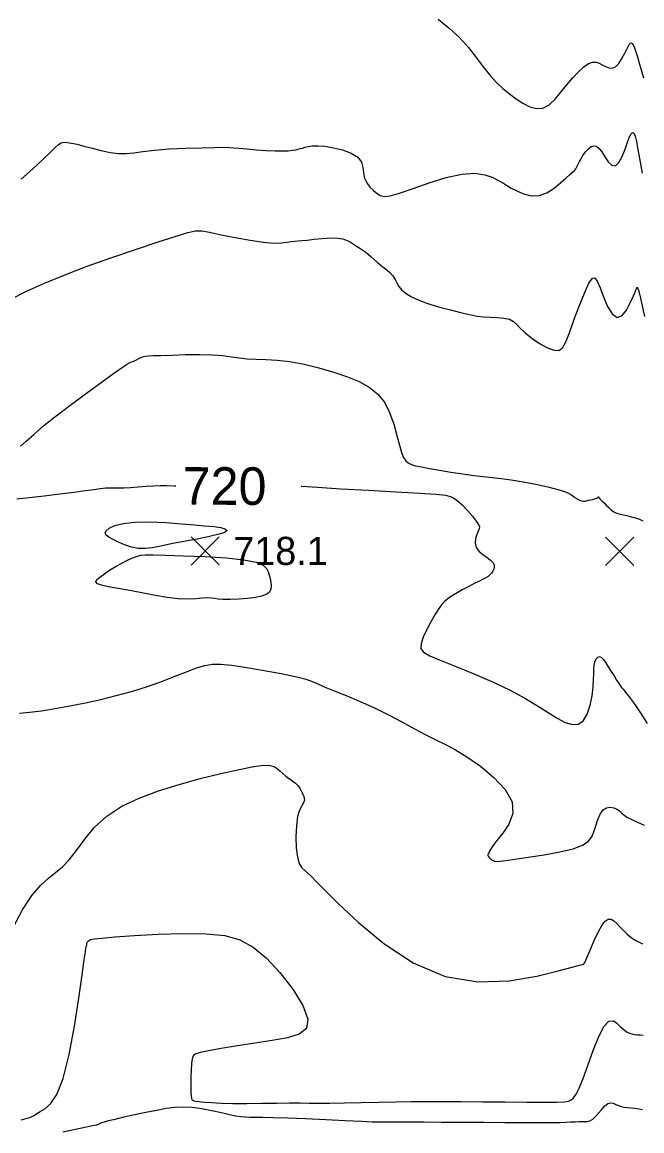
# Model space of a CAD drawing. Extents: x 2566142 to 2571431, y 418755 to 421584.
# Drawn here: x 2570491 to 2570821, y 419211 to 419801 of the extents above; entities that cross this region are included whole.
import ezdxf

# ---------------------------------------------------------------- set-up
doc = ezdxf.new("R2010")
doc.units = 0
for name, color, linetype in [('Contour_ADS_Label_Major', 7, 'Continuous'), ('Contour_ADS_Major', 7, 'Continuous'), ('Contour_ADS_Minor', 7, 'Continuous'), ('Contour_ADS_Spot_Elevation', 7, 'Continuous')]:
    doc.layers.add(name, color=color, linetype=linetype)

# ---------------------------------------------------------------- blocks, each defined once
blk = doc.blocks.new('S750')
at = {"layer": 'Contour_ADS_Spot_Elevation'}
for p, q in [((-0.5, 0.498), (0.5, -0.498)), ((-0.498, -0.5), (0.498, 0.5))]:
    blk.add_line(p, q, dxfattribs=at)

msp = doc.modelspace()

# ---------------------------------------------------------------- linework, layer by layer
at = {"layer": 'Contour_ADS_Major'}
for points in [[(2570488.33, 419547.23), (2570494.91, 419547.98), (2570502.85, 419548.9), (2570511.1, 419549.89), (2570518.65, 419550.84), (2570524.68, 419551.67), (2570529.29, 419552.33), (2570532.8, 419552.81), (2570535.53, 419553.08), (2570537.82, 419553.16), (2570539.98, 419553.11), (2570542.33, 419553.06), (2570545.19, 419553.11), (2570548.77, 419553.32), (2570552.83, 419553.65), (2570557.04, 419553.99), (2570561.03, 419554.26), (2570564.61, 419554.36), (2570568.09, 419554.33), (2570571.93, 419554.2), (2570572.86, 419554.16)], [(2570639.53, 419553.98), (2570639.84, 419553.95), (2570648.19, 419553.41), (2570660.55, 419552.68), (2570675.25, 419551.85), (2570689.99, 419551.04), (2570702.51, 419550.33), (2570711.11, 419549.79), (2570716.46, 419549.17), (2570719.78, 419548.18), (2570722.33, 419546.53), (2570725.08, 419544.03), (2570727.94, 419541.04), (2570730.57, 419538.03), (2570732.62, 419535.47), (2570733.83, 419533.7), (2570734.29, 419532.46), (2570734.17, 419531.39), (2570733.64, 419530.09), (2570732.91, 419528.28), (2570732.27, 419526.09), (2570732.06, 419523.74), (2570732.59, 419521.46), (2570734.06, 419519.41), (2570736.15, 419517.62), (2570738.38, 419516.03), (2570740.3, 419514.61), (2570741.54, 419513.33), (2570742.15, 419512.15), (2570742.25, 419511.03), (2570741.99, 419509.94), (2570741.5, 419508.86), (2570740.8, 419507.82), (2570739.94, 419506.85), (2570738.94, 419505.98), (2570737.78, 419505.22), (2570736.34, 419504.46), (2570734.44, 419503.55), (2570731.92, 419502.33), (2570728.7, 419500.71), (2570725.11, 419498.79), (2570721.54, 419496.74), (2570718.42, 419494.72), (2570716.02, 419492.81), (2570714.15, 419490.82), (2570712.47, 419488.48), (2570710.67, 419485.53), (2570708.54, 419481.83), (2570706.34, 419477.74), (2570704.47, 419473.73), (2570703.31, 419470.29), (2570703.25, 419467.73), (2570704.67, 419465.73), (2570707.96, 419463.79), (2570713.5, 419461.42), (2570721.43, 419458.25), (2570730.92, 419454.4), (2570740.93, 419450.13), (2570750.38, 419445.69), (2570758.44, 419441.32), (2570765.16, 419437.22), (2570770.82, 419433.56), (2570775.7, 419430.53), (2570780.01, 419428.34), (2570783.79, 419427.22), (2570787.02, 419427.45), (2570789.66, 419429.28), (2570791.72, 419432.8), (2570793.23, 419437.47), (2570794.25, 419442.55), (2570794.85, 419447.32), (2570795.09, 419451.2), (2570795.13, 419454.27), (2570795.14, 419456.72), (2570795.31, 419458.78), (2570795.75, 419460.61), (2570796.44, 419462.09), (2570797.31, 419463.06), (2570798.28, 419463.37), (2570799.29, 419462.9), (2570800.37, 419461.74), (2570801.56, 419460.02), (2570802.89, 419457.9), (2570804.38, 419455.51), (2570805.91, 419453.1), (2570807.31, 419450.88), (2570808.44, 419449.11), (2570809.22, 419447.92), (2570809.88, 419446.99), (2570810.7, 419445.94), (2570812.01, 419444.35), (2570814.02, 419441.87), (2570816.68, 419438.34), (2570819.89, 419433.66), (2570823.51, 419427.73)]]:
    msp.add_lwpolyline(points, dxfattribs=at)
at = {"layer": 'Contour_ADS_Minor'}
for points in [[(2570712.43, 419802.4), (2570718.23, 419797.74), (2570723.68, 419792.69), (2570728.44, 419787.42), (2570732.59, 419782.14), (2570736.32, 419777.12), (2570739.85, 419772.6), (2570743.33, 419768.77), (2570746.81, 419765.51), (2570750.32, 419762.69)], [(2570750.32, 419762.69), (2570753.87, 419760.12), (2570757.47, 419757.74), (2570761.08, 419755.84), (2570764.64, 419754.84), (2570768.08, 419755.11), (2570771.38, 419756.92), (2570774.56, 419759.91), (2570777.69, 419763.61), (2570780.8, 419767.52), (2570783.93, 419771.21), (2570786.98, 419774.44), (2570789.84, 419777.03), (2570792.38, 419778.78), (2570794.53, 419779.58), (2570796.37, 419779.6), (2570798.05, 419779.05), (2570799.68, 419778.18), (2570801.38, 419777.23), (2570803.14, 419776.51), (2570804.93, 419776.35), (2570806.73, 419777.07), (2570808.49, 419778.88), (2570810.16, 419781.44), (2570811.67, 419784.28), (2570812.94, 419786.92), (2570813.95, 419788.92), (2570814.82, 419789.88), (2570815.72, 419789.42), (2570816.84, 419787.17), (2570818.28, 419782.95), (2570819.91, 419777.35), (2570821.55, 419771.17)], [(2570686.92, 419708.47), (2570691.89, 419709.84), (2570699.05, 419712.33), (2570707.65, 419715.35), (2570716.64, 419718.17), (2570724.97, 419720.05), (2570731.8, 419720.45), (2570737.13, 419719.7), (2570741.15, 419718.32), (2570744.04, 419716.86), (2570746.06, 419715.72), (2570747.63, 419714.79), (2570749.21, 419713.84), (2570751.3, 419712.63), (2570754.23, 419711.05), (2570757.86, 419709.5), (2570761.92, 419708.5), (2570766.13, 419708.57), (2570770.24, 419710.05), (2570774.07, 419712.51), (2570777.46, 419715.34), (2570780.25, 419717.93), (2570782.34, 419719.81), (2570783.83, 419721.09), (2570784.86, 419722.03), (2570785.58, 419722.86), (2570786.15, 419723.82), (2570786.69, 419724.96), (2570787.32, 419726.33), (2570788.19, 419727.97), (2570789.37, 419729.86), (2570790.78, 419731.79), (2570792.3, 419733.49), (2570793.81, 419734.68), (2570795.22, 419735.15), (2570796.57, 419734.84), (2570797.94, 419733.73), (2570799.43, 419731.82), (2570801.1, 419729.23), (2570802.89, 419726.61), (2570804.76, 419724.75), (2570806.65, 419724.44), (2570808.48, 419726.19), (2570810.21, 419729.44), (2570811.78, 419733.33), (2570813.13, 419737.02), (2570814.21, 419739.8), (2570815.09, 419741.52), (2570815.82, 419742.17), (2570816.47, 419741.72), (2570817.12, 419740.13), (2570817.82, 419737.32), (2570818.65, 419733.15), (2570819.66, 419727.5), (2570820.88, 419720.44)], [(2570490.64, 419717.28), (2570496.87, 419722.8), (2570502.02, 419727.68), (2570505.96, 419731.57), (2570508.67, 419734.25), (2570510.49, 419735.86), (2570511.88, 419736.67), (2570513.28, 419736.93), (2570515.07, 419736.87), (2570517.4, 419736.51), (2570520.34, 419735.87), (2570523.97, 419734.95), (2570528.31, 419733.78), (2570533.06, 419732.57), (2570537.87, 419731.54), (2570542.39, 419730.95), (2570546.44, 419730.95), (2570550.51, 419731.4), (2570555.29, 419732.1), (2570561.47, 419732.82), (2570569.4, 419733.4), (2570578.21, 419733.81), (2570586.7, 419734.08), (2570593.69, 419734.23), (2570598.35, 419734.28), (2570601.35, 419734.24), (2570603.76, 419734.08), (2570606.62, 419733.81), (2570610.71, 419733.43), (2570615.66, 419733.02), (2570620.86, 419732.65), (2570625.65, 419732.41), (2570629.54, 419732.36), (2570632.56, 419732.46), (2570634.86, 419732.68), (2570636.61, 419732.95), (2570637.97, 419733.25), (2570639.13, 419733.56), (2570640.27, 419733.9), (2570641.58, 419734.29), (2570643.24, 419734.69), (2570645.43, 419735.01), (2570648.3, 419735.1), (2570652.03, 419734.83), (2570656.63, 419734.09), (2570661.56, 419732.86), (2570666.11, 419731.16), (2570669.6, 419728.99), (2570671.54, 419726.4), (2570672.36, 419723.55), (2570672.69, 419720.63), (2570673.2, 419717.83), (2570674.36, 419715.31), (2570676.05, 419713.11), (2570677.98, 419711.26), (2570679.87, 419709.76), (2570681.61, 419708.66), (2570683.72, 419708.16), (2570686.92, 419708.47)], [(2570484.67, 419653.26), (2570493.41, 419657.68), (2570502.93, 419662), (2570513.46, 419666.33), (2570525.25, 419670.8), (2570538.26, 419675.43), (2570551.44, 419679.93), (2570563.47, 419683.93), (2570573.03, 419687.04), (2570579.27, 419689), (2570583.28, 419689.87), (2570586.6, 419689.84), (2570590.78, 419689.08), (2570596.95, 419687.79), (2570604.48, 419686.27), (2570612.32, 419684.82), (2570619.42, 419683.77), (2570624.95, 419683.34), (2570629.03, 419683.4), (2570632.01, 419683.73), (2570634.24, 419684.11), (2570636.07, 419684.37), (2570637.85, 419684.54), (2570639.96, 419684.71), (2570642.76, 419684.97), (2570646.48, 419685.37)], [(2570646.48, 419685.37), (2570650.74, 419685.78), (2570655.03, 419686.05), (2570658.83, 419686), (2570661.77, 419685.54), (2570663.99, 419684.75), (2570665.77, 419683.75), (2570667.37, 419682.67), (2570669.03, 419681.63), (2570670.73, 419680.6), (2570672.4, 419679.56), (2570673.96, 419678.45), (2570675.38, 419677.25), (2570676.78, 419675.94), (2570678.28, 419674.53), (2570680.05, 419673), (2570682.15, 419671.36), (2570684.4, 419669.62), (2570686.53, 419667.8), (2570688.29, 419665.93), (2570689.52, 419664.03), (2570690.47, 419662.11), (2570691.52, 419660.21), (2570693.03, 419658.33), (2570695.28, 419656.51), (2570698.24, 419654.75), (2570701.78, 419653.1), (2570705.78, 419651.57), (2570710.11, 419650.18), (2570714.56, 419648.93), (2570718.92, 419647.8), (2570722.97, 419646.79), (2570726.58, 419645.88), (2570729.9, 419645.11), (2570733.14, 419644.51), (2570736.52, 419644.11), (2570740.18, 419643.91), (2570743.89, 419643.75), (2570747.35, 419643.45), (2570750.24, 419642.82), (2570752.38, 419641.69), (2570754.16, 419640.07), (2570756.08, 419638), (2570758.64, 419635.51), (2570762.18, 419632.69), (2570766.31, 419629.93), (2570770.45, 419627.64), (2570774.02, 419626.28), (2570776.63, 419626.22), (2570778.55, 419627.66), (2570780.25, 419630.76), (2570782.17, 419635.66), (2570784.63, 419642.3), (2570787.42, 419649.7), (2570790.19, 419656.65), (2570792.6, 419661.95), (2570794.4, 419664.67), (2570795.78, 419664.91), (2570797.04, 419663.06), (2570798.48, 419659.47), (2570800.32, 419654.66), (2570802.52, 419649.66), (2570804.96, 419645.61), (2570807.52, 419643.68), (2570810.08, 419644.62), (2570812.49, 419647.66), (2570814.59, 419651.61), (2570816.24, 419655.28), (2570817.31, 419657.76), (2570817.93, 419659.11), (2570818.22, 419659.68), (2570818.35, 419659.78), (2570818.44, 419659.7), (2570818.51, 419659.53), (2570818.58, 419659.31), (2570818.66, 419659.08), (2570818.74, 419658.86), (2570818.84, 419658.64), (2570818.94, 419658.38), (2570819.04, 419658.05), (2570819.18, 419657.44), (2570819.57, 419655.65), (2570820.45, 419651.63), (2570822.06, 419644.32)], [(2570547.91, 419619.4), (2570548.97, 419619.91), (2570549.9, 419620.3), (2570550.88, 419620.72), (2570552, 419621.26), (2570553.22, 419621.87), (2570554.46, 419622.45), (2570555.62, 419622.91), (2570556.74, 419623.19), (2570558.27, 419623.34), (2570560.78, 419623.44), (2570564.85, 419623.57), (2570570.79, 419623.78), (2570577.95, 419623.98), (2570585.42, 419624.07), (2570592.28, 419623.94), (2570597.87, 419623.5), (2570602.47, 419622.89), (2570606.6, 419622.26), (2570610.78, 419621.79), (2570615.45, 419621.56), (2570620.75, 419621.4), (2570626.76, 419621.05), (2570633.55, 419620.27), (2570641.09, 419618.88), (2570649, 419616.96), (2570656.82, 419614.69), (2570664.08, 419612.23), (2570670.39, 419609.66), (2570675.74, 419606.76), (2570680.17, 419603.22), (2570683.76, 419598.73), (2570686.58, 419593.17), (2570688.75, 419587.04), (2570690.43, 419581.04), (2570691.77, 419575.85), (2570692.9, 419571.99), (2570693.97, 419569.33), (2570695.11, 419567.57), (2570696.45, 419566.4), (2570698.13, 419565.56), (2570700.4, 419564.88), (2570703.51, 419564.23), (2570707.69, 419563.48), (2570713.06, 419562.54), (2570719.18, 419561.51), (2570725.47, 419560.52), (2570731.36, 419559.7), (2570736.45, 419559.12), (2570741.1, 419558.67), (2570745.85, 419558.17), (2570751.23, 419557.44), (2570757.58, 419556.35), (2570764.34, 419555.02), (2570770.73, 419553.62), (2570775.98, 419552.32), (2570779.52, 419551.25), (2570781.67, 419550.36), (2570782.98, 419549.58), (2570783.97, 419548.83), (2570785.08, 419548.04), (2570786.31, 419547.28), (2570787.54, 419546.64), (2570788.68, 419546.19), (2570789.64, 419546.02), (2570790.49, 419546.06), (2570791.33, 419546.23), (2570792.26, 419546.48), (2570793.34, 419546.72), (2570794.48, 419546.96), (2570795.55, 419547.2), (2570796.41, 419547.45), (2570796.98, 419547.72), (2570797.3, 419547.96), (2570797.46, 419548.16), (2570797.53, 419548.29), (2570797.59, 419548.31), (2570797.68, 419548.22), (2570797.83, 419548.03), (2570798.08, 419547.74), (2570798.45, 419547.34), (2570798.98, 419546.79), (2570799.7, 419546.07), (2570800.65, 419545.12), (2570801.82, 419543.93), (2570803.14, 419542.65), (2570804.48, 419541.43), (2570805.74, 419540.43), (2570806.85, 419539.78), (2570807.94, 419539.39), (2570809.17, 419539.1), (2570810.73, 419538.8), (2570812.72, 419538.36), (2570814.98, 419537.79), (2570817.29, 419537.13), (2570819.43, 419536.4), (2570821.21, 419535.63)], [(2570490.16, 419575.22), (2570493.24, 419577.9), (2570497.26, 419581.55), (2570502.71, 419586.24), (2570509.84, 419591.92), (2570517.92, 419598.07), (2570525.98, 419604.05), (2570533.06, 419609.21), (2570538.41, 419613.07), (2570542.2, 419615.76), (2570544.8, 419617.53), (2570546.59, 419618.66), (2570547.91, 419619.4)], [(2570489.66, 419433.3), (2570494.99, 419433.73), (2570501.41, 419434.53), (2570508.7, 419435.68), (2570516.57, 419437.11), (2570524.75, 419438.76), (2570532.98, 419440.58), (2570541.16, 419442.58), (2570549.25, 419444.79), (2570557.18, 419447.27), (2570564.85, 419449.99), (2570572.03, 419452.74), (2570578.47, 419455.28), (2570583.88, 419457.33), (2570588.2, 419458.69), (2570592.16, 419459.35), (2570596.68, 419459.35), (2570602.67, 419458.73), (2570610.7, 419457.56), (2570619.84, 419456.03)], [(2570619.84, 419456.03), (2570628.81, 419454.38), (2570636.31, 419452.82), (2570641.47, 419451.5), (2570645, 419450.29), (2570648.06, 419448.97), (2570651.76, 419447.33), (2570656.99, 419445.2), (2570663.51, 419442.58), (2570670.83, 419439.53), (2570678.45, 419436.1), (2570685.94, 419432.37), (2570693.08, 419428.56), (2570699.74, 419424.92), (2570705.77, 419421.71), (2570711.12, 419419.04), (2570716.21, 419416.54), (2570721.56, 419413.68), (2570727.69, 419409.95), (2570734.83, 419404.99), (2570742.03, 419399.08), (2570748.06, 419392.64), (2570751.69, 419386.12), (2570752.08, 419379.89), (2570750.06, 419374.23), (2570746.85, 419369.34), (2570743.66, 419365.43), (2570741.48, 419362.64), (2570740.22, 419360.8), (2570739.59, 419359.66), (2570739.26, 419358.96), (2570738.98, 419358.49), (2570738.77, 419358.11), (2570738.73, 419357.71), (2570738.95, 419357.21), (2570739.49, 419356.54), (2570740.29, 419355.78), (2570741.27, 419355.09), (2570742.32, 419354.58), (2570743.49, 419354.37), (2570745.27, 419354.48), (2570748.31, 419354.9), (2570753.22, 419355.62), (2570760.33, 419356.64), (2570768.71, 419357.92), (2570777.09, 419359.42), (2570784.22, 419361.1), (2570789.18, 419362.95), (2570792.25, 419365.03), (2570794.06, 419367.41), (2570795.22, 419370.2), (2570796.26, 419373.38), (2570797.36, 419376.63), (2570798.62, 419379.56), (2570800.14, 419381.75), (2570801.94, 419382.91), (2570803.9, 419383.19), (2570805.8, 419382.83), (2570807.47, 419382.11), (2570808.78, 419381.22), (2570809.92, 419380.23), (2570811.18, 419379.14), (2570812.82, 419377.98), (2570815.01, 419376.78), (2570817.5, 419375.6), (2570819.93, 419374.54), (2570821.93, 419373.69)], [(2570486.13, 419318.8), (2570491.3, 419328.68), (2570496.32, 419336.19), (2570500.98, 419341.67), (2570505.13, 419345.55), (2570508.91, 419348.55), (2570512.51, 419351.5), (2570516.13, 419355.21), (2570519.98, 419360.26), (2570524.39, 419366.25), (2570529.68, 419372.55), (2570536.2, 419378.53), (2570544.18, 419383.71), (2570553.44, 419388.11), (2570563.68, 419391.92), (2570574.62, 419395.32), (2570585.89, 419398.44), (2570596.78, 419401.17), (2570606.53, 419403.35), (2570614.34, 419404.83), (2570619.7, 419405.51), (2570623.07, 419405.47), (2570625.15, 419404.87), (2570626.68, 419403.86), (2570628.21, 419402.57), (2570629.81, 419401.17), (2570631.39, 419399.81), (2570632.85, 419398.63), (2570634.15, 419397.72), (2570635.34, 419396.92), (2570636.5, 419396), (2570637.69, 419394.75), (2570638.97, 419393.01), (2570640.13, 419390.96), (2570640.95, 419388.88), (2570641.21, 419387.01), (2570640.75, 419385.5), (2570639.8, 419383.91), (2570638.65, 419381.67), (2570637.62, 419378.24), (2570636.96, 419373.27), (2570636.71, 419367.42), (2570636.89, 419361.58), (2570637.5, 419356.63), (2570638.52, 419353.21), (2570639.86, 419351.03), (2570641.41, 419349.55), (2570643.06, 419348.22), (2570644.87, 419346.49)], [(2570644.87, 419346.49), (2570647.58, 419343.66), (2570652.1, 419339.02), (2570659.37, 419331.85), (2570670, 419321.9), (2570683.5, 419310.76), (2570699.11, 419300.51), (2570716.03, 419293.21), (2570733.42, 419290.33), (2570750.09, 419290.91), (2570764.79, 419293.39), (2570776.25, 419296.22), (2570783.61, 419298.15), (2570787.57, 419299.18), (2570789.25, 419299.62), (2570789.74, 419299.79), (2570790, 419300), (2570790.35, 419300.61), (2570790.96, 419301.94), (2570791.98, 419304.35), (2570793.53, 419308.01), (2570795.44, 419312.36), (2570797.51, 419316.69), (2570799.51, 419320.28), (2570801.28, 419322.56), (2570802.87, 419323.6), (2570804.35, 419323.6), (2570805.84, 419322.78), (2570807.41, 419321.36), (2570809.09, 419319.57), (2570810.91, 419317.6), (2570812.88, 419315.68), (2570815, 419313.99), (2570817.16, 419312.56), (2570819.21, 419311.39), (2570821, 419310.47)], [(2570490.64, 419216.86), (2570494.73, 419217.99), (2570497.21, 419219.1), (2570498.92, 419220.22), (2570500.68, 419221.38), (2570503.14, 419222.77), (2570506.2, 419225.39), (2570509.57, 419230.4), (2570512.97, 419238.98), (2570516.12, 419251.7), (2570518.92, 419266.73), (2570521.24, 419281.64), (2570522.99, 419294), (2570524.12, 419302.01), (2570524.74, 419306.32), (2570525.04, 419308.18), (2570525.18, 419308.88), (2570525.31, 419309.45), (2570525.46, 419310.05), (2570525.61, 419310.65), (2570525.77, 419311.17), (2570525.94, 419311.59), (2570526.15, 419311.93), (2570526.45, 419312.21), (2570526.88, 419312.48), (2570527.64, 419312.78), (2570529.51, 419313.14), (2570533.44, 419313.61), (2570540.36, 419314.24), (2570550.79, 419315.01), (2570563.47, 419315.73), (2570576.76, 419316.12), (2570588.98, 419315.94), (2570598.88, 419314.9), (2570606.92, 419312.66), (2570613.95, 419308.85), (2570620.84, 419303.11), (2570628.13, 419295.33), (2570635.03, 419286.49), (2570640.4, 419277.81), (2570643.13, 419270.51), (2570642.39, 419265.52), (2570638.54, 419262.43), (2570632.23, 419260.56), (2570624.13, 419259.18), (2570614.94, 419257.74), (2570605.58, 419256.23), (2570597.01, 419254.8), (2570590.2, 419253.58), (2570585.84, 419252.67), (2570583.52, 419252.02), (2570582.53, 419251.53), (2570582.2, 419251.1), (2570581.94, 419250.6), (2570581.65, 419249.82), (2570581.38, 419248.52), (2570581.14, 419246.45), (2570580.96, 419243.5), (2570580.83, 419240.02), (2570580.77, 419236.49), (2570580.78, 419233.38), (2570580.85, 419231.07), (2570580.99, 419229.48), (2570581.18, 419228.45), (2570581.42, 419227.8), (2570581.74, 419227.38), (2570582.35, 419227.1), (2570583.46, 419226.88), (2570585.32, 419226.66), (2570588.12, 419226.37), (2570591.98, 419226.07), (2570596.98, 419225.8), (2570603.21, 419225.64), (2570610.61, 419225.62), (2570618.58, 419225.7), (2570626.4, 419225.81), (2570633.32, 419225.89), (2570638.9, 419225.89), (2570643.74, 419225.85), (2570648.75, 419225.81), (2570654.81, 419225.83), (2570662.56, 419225.95), (2570671.5, 419226.13), (2570680.88, 419226.34), (2570689.97, 419226.52), (2570698.24, 419226.64), (2570706.24, 419226.7), (2570714.73, 419226.7), (2570724.48, 419226.65), (2570735.93, 419226.56), (2570748.07, 419226.46), (2570759.56, 419226.37), (2570769.04, 419226.32), (2570775.53, 419226.34)], [(2570775.53, 419226.34), (2570779.51, 419226.5), (2570781.78, 419226.87), (2570783.19, 419227.53), (2570784.44, 419228.61), (2570785.81, 419230.54), (2570787.44, 419233.79), (2570789.48, 419238.84), (2570792.02, 419245.86), (2570794.89, 419253.78), (2570797.86, 419261.19), (2570800.7, 419266.72), (2570803.22, 419269.35), (2570805.41, 419269.63), (2570807.3, 419268.49), (2570808.95, 419266.83), (2570810.39, 419265.43), (2570811.69, 419264.39), (2570812.92, 419263.62), (2570814.17, 419263.06), (2570815.48, 419262.64), (2570816.87, 419262.35), (2570818.33, 419262.17), (2570819.84, 419262.08), (2570821.39, 419261.99)], [(2570512.81, 419210.46), (2570519.56, 419212.02), (2570524.45, 419213.08), (2570527.66, 419213.72), (2570529.62, 419214.08), (2570530.76, 419214.29), (2570531.44, 419214.48), (2570531.89, 419214.68), (2570532.28, 419214.9), (2570532.76, 419215.16), (2570533.54, 419215.47), (2570534.89, 419215.89), (2570537.12, 419216.49), (2570540.52, 419217.33), (2570545.26, 419218.43), (2570550.91, 419219.69), (2570556.9, 419220.97), (2570562.65, 419222.13), (2570567.74, 419223.05), (2570572.37, 419223.64), (2570576.87, 419223.85), (2570581.6, 419223.6), (2570586.77, 419222.88), (2570592.09, 419221.85), (2570597.13, 419220.74), (2570601.48, 419219.75), (2570604.85, 419219.06), (2570607.5, 419218.64), (2570609.85, 419218.43), (2570612.3, 419218.36), (2570615.26, 419218.34), (2570619.22, 419218.32), (2570624.69, 419218.24), (2570632.17, 419218.02), (2570641.83, 419217.62), (2570652.57, 419217.12), (2570662.95, 419216.62), (2570671.53, 419216.19), (2570677.32, 419215.93), (2570681.05, 419215.81), (2570683.9, 419215.77), (2570687.03, 419215.78), (2570691.43, 419215.8), (2570697.37, 419215.8), (2570704.94, 419215.79), (2570714.22, 419215.76), (2570725.11, 419215.7), (2570736.69, 419215.63), (2570747.85, 419215.55), (2570757.49, 419215.49), (2570764.78, 419215.46), (2570770.06, 419215.46), (2570773.97, 419215.49), (2570777.15, 419215.56), (2570780.09, 419215.66), (2570782.82, 419215.78), (2570785.24, 419215.89), (2570787.24, 419215.96), (2570788.75, 419215.97), (2570789.89, 419215.96), (2570790.79, 419215.95), (2570791.62, 419215.99), (2570792.49, 419216.13), (2570793.47, 419216.49), (2570794.6, 419217.21), (2570795.93, 419218.45), (2570797.48, 419220.26), (2570799.17, 419222.31), (2570800.89, 419224.2), (2570802.55, 419225.52), (2570804.07, 419225.97), (2570805.48, 419225.74), (2570806.86, 419225.15), (2570808.26, 419224.5), (2570809.74, 419224.04), (2570811.34, 419223.74), (2570813.07, 419223.54), (2570814.96, 419223.33), (2570817.01, 419223.07), (2570819.1, 419222.77), (2570821.09, 419222.49)]]:
    msp.add_lwpolyline(points, dxfattribs=at)
for points in [[(2570570.37, 419523.26), (2570564.86, 419522.12), (2570560.36, 419521.26), (2570556.48, 419520.81), (2570552.87, 419520.91), (2570549.22, 419521.64), (2570545.63, 419522.81), (2570542.31, 419524.21), (2570539.45, 419525.62), (2570537.23, 419526.85), (2570535.79, 419527.97), (2570535.26, 419529.09), (2570535.76, 419530.31), (2570537.43, 419531.7), (2570540.44, 419533.07), (2570544.94, 419534.22), (2570551.11, 419534.91), (2570558.92, 419534.99), (2570567.51, 419534.62), (2570575.85, 419534.02), (2570582.89, 419533.41), (2570587.85, 419532.96), (2570591.03, 419532.67), (2570593.01, 419532.48), (2570594.37, 419532.33), (2570595.6, 419532.18), (2570596.76, 419531.99), (2570597.87, 419531.72), (2570598.89, 419531.35), (2570599.73, 419530.86), (2570599.9, 419530.22), (2570598.81, 419529.41), (2570595.87, 419528.4), (2570590.75, 419527.21), (2570584.16, 419525.89), (2570577.05, 419524.55), (2570570.37, 419523.26)], [(2570609.08, 419514.88), (2570615.52, 419513.56), (2570619.27, 419511.92), (2570621.21, 419509.99), (2570622.19, 419507.83), (2570622.91, 419505.5), (2570623.41, 419503.14), (2570623.58, 419500.92), (2570623.31, 419499), (2570622.47, 419497.49), (2570620.93, 419496.35), (2570618.58, 419495.5), (2570615.29, 419494.85), (2570611.03, 419494.33), (2570606.32, 419493.96), (2570601.75, 419493.76), (2570597.94, 419493.76), (2570595.29, 419493.97), (2570593.45, 419494.27), (2570591.84, 419494.52), (2570589.88, 419494.59), (2570587.12, 419494.39), (2570583.5, 419494.09), (2570579.1, 419493.93), (2570573.97, 419494.11), (2570568.21, 419494.81), (2570562.03, 419495.89), (2570555.65, 419497.14), (2570549.33, 419498.35), (2570543.32, 419499.36), (2570538.01, 419500.25), (2570533.83, 419501.1), (2570531.19, 419502.04), (2570530.34, 419503.15), (2570530.92, 419504.37), (2570532.38, 419505.65), (2570534.18, 419506.91), (2570535.89, 419508.1), (2570537.58, 419509.26), (2570539.41, 419510.45), (2570541.53, 419511.72), (2570544.06, 419513.1), (2570546.81, 419514.48), (2570549.53, 419515.71), (2570551.96, 419516.67), (2570554.08, 419517.23), (2570556.68, 419517.46), (2570560.75, 419517.44), (2570567.31, 419517.26), (2570576.91, 419516.97), (2570588.24, 419516.52), (2570599.55, 419515.85), (2570609.08, 419514.88)]]:
    msp.add_lwpolyline(points, close=True, dxfattribs=at)

# ---------------------------------------------------------------- block references
at = {"layer": 'Contour_ADS_Spot_Elevation', "xscale": 15, "yscale": 15}
for p in [(2570588.44, 419519.56), (2570808.94, 419519.35)]:
    msp.add_blockref('S750', p, dxfattribs=at)

# ---------------------------------------------------------------- texts
at = {"layer": 'Contour_ADS_Label_Major'}
msp.add_text('720', height=20, rotation=359.84183, dxfattribs=at).set_placement((2570576.44, 419544.15))
at = {"layer": 'Contour_ADS_Spot_Elevation'}
msp.add_text('718.1', height=15, dxfattribs=at).set_placement((2570603.44, 419512.06))

doc.saveas('drawing.dxf')
